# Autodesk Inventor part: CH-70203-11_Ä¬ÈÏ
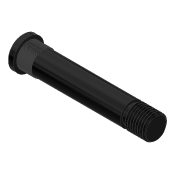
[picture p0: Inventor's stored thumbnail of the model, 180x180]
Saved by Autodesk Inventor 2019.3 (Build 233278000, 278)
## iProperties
Created: 2010-06
Part Number: CH-70203-11_Ä¬ÈÏ
Material: Ogólny
Document SubType Name: Modeling
Designer: CADENGINEERING4
Density: 1 g/cm^3
Appearance: Gładki — czarny
Author: CADENGINEERING4
Revision Number: ÈÎºÎ
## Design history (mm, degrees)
feature "NONE"
node "Bryła1"
